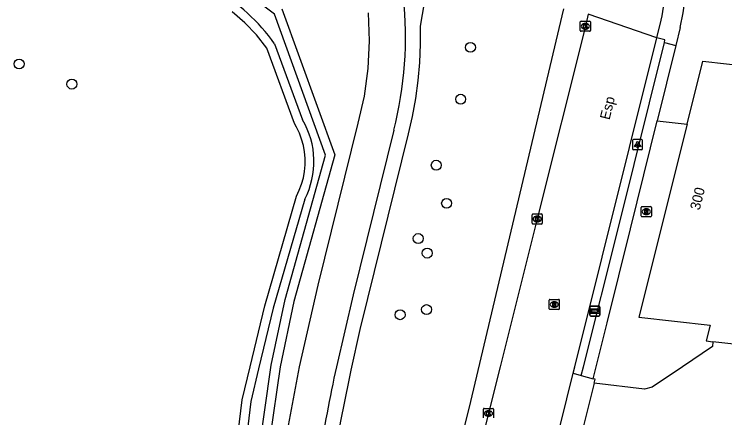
# Model space of a CAD drawing. Extents: x 161389 to 162585, y 388479 to 389761.
# Drawn here: x 162161.9 to 162232.2, y 388744.9 to 388784.9 of the extents above; entities that cross this region are included whole.
import ezdxf

# ---------------------------------------------------------------- set-up
doc = ezdxf.new("R2010")
doc.units = 0
for name, color, linetype in [('IMGEO_Berm_groen', 7, 'Continuous'), ('IMGEO_Boom', 7, 'Continuous'), ('IMGEO_Fietspad_gesloten', 7, 'Continuous'), ('IMGEO_Groenvoorziening', 7, 'Continuous'), ('IMGEO_Kolk', 7, 'Continuous'), ('IMGEO_Lichtpunt', 7, 'Continuous'), ('IMGEO_Openbare_ruimte_label', 7, 'Continuous'), ('IMGEO_Pand', 7, 'Continuous'), ('IMGEO_Pand_nummerreeks', 7, 'Continuous'), ('IMGEO_Rijbaan_lokaal_gesloten', 7, 'Continuous'), ('IMGEO_Rioolput', 7, 'Continuous'), ('IMGEO_Voetpad_open', 7, 'Continuous'), ('IMGEO_Waterloop', 7, 'Continuous'), ('IMGEO_Wegwijzer', 7, 'Continuous')]:
    doc.layers.add(name, color=color, linetype=linetype)

msp = doc.modelspace()

# ---------------------------------------------------------------- linework, layer by layer
at = {"layer": 'IMGEO_Berm_groen'}
for points in [[(162191.86, 388718.037), (162191.886, 388722.099), (162191.891, 388724.822), (162191.975, 388727.523), (162192.137, 388730.219), (162192.378, 388732.909), (162192.697, 388735.591), (162193.094, 388738.264), (162193.499, 388740.561), (162194.225, 388744.62), (162195.027, 388748.658), (162195.242, 388749.672), (162196.145, 388753.699), (162196.882, 388756.748), (162200.909, 388773.061), (162201.309, 388774.777), (162201.634, 388776.543), (162201.879, 388778.321), (162202.04, 388780.111), (162202.118, 388781.905), (162202.114, 388783.702), (162202.484, 388786.004)], [(162216.273, 388785.418), (162206.891, 388745.858), (162201.753, 388725.36), (162199.91, 388717.985), (162191.86, 388718.037)]]:
    msp.add_lwpolyline(points, dxfattribs=at)
at = {"layer": 'IMGEO_Boom'}
for centre in [(162207.051, 388781.607), (162162.37, 388779.96), (162167.587, 388777.964), (162206.084, 388776.477), (162203.663, 388769.943), (162204.685, 388766.173), (162201.877, 388762.686), (162202.768, 388761.243), (162202.7, 388755.656), (162200.089, 388755.143)]:
    msp.add_circle(centre, 0.489, dxfattribs=at)
at = {"layer": 'IMGEO_Fietspad_gesloten'}
for points in [[(162186.329, 388700.295), (162186.802, 388723.126), (162187.239, 388731.997), (162188.536, 388741.532), (162190.109, 388750), (162191.97, 388758.076), (162195.928, 388774.095), (162196.55, 388776.78), (162196.93, 388779.509), (162197.064, 388782.261), (162196.952, 388785.015)], [(162199.448, 388773.401), (162195.426, 388757.107), (162193.778, 388750)]]:
    msp.add_lwpolyline(points, dxfattribs=at)
for centre, radius, start, end in [((162163.354, 388782.698), 37.273, 345.55573, 5.99964), ((162403.128, 388705.189), 214.092, 167.91817, 170.41916)]:
    msp.add_arc(centre, radius, start, end, dxfattribs=at)
at = {"layer": 'IMGEO_Groenvoorziening'}
for points in [[(162188.39, 388785.424), (162193.632, 388770.975), (162189.553, 388756.443), (162188.194, 388750), (162186.166, 388735.884), (162185.429, 388723.281), (162185.919, 388717.086), (162185.324, 388714.25), (162184.667, 388702.506)], [(162181.617, 388706.073), (162182.042, 388714.232), (162182.441, 388730.142), (162184.437, 388746.716), (162185.228, 388750), (162186.682, 388756.035), (162189.827, 388766.893), (162190.106, 388767.475), (162190.333, 388768.079), (162190.504, 388768.701), (162190.619, 388769.336), (162190.677, 388769.979), (162190.678, 388770.624), (162190.62, 388771.267), (162190.506, 388771.902), (162190.335, 388772.525), (162190.109, 388773.129), (162189.831, 388773.711), (162189.63, 388774.062), (162186.881, 388781.532), (162185.852, 388782.834), (162184.71, 388784.039), (162183.465, 388785.137)], [(162225.536, 388774.348), (162228.503, 388774.016)], [(162231.056, 388752.479), (162231.003, 388751.998), (162228.046, 388750), (162225.043, 388747.971), (162224.275, 388747.77), (162219.301, 388748.377)]]:
    msp.add_lwpolyline(points, dxfattribs=at)
at = {"layer": 'IMGEO_Kolk'}
for p, q in [((162217.921, 388783.266), (162217.921, 388784.118)), ((162217.996, 388784.192), (162218.848, 388784.192)), ((162218.409, 388783.972), (162218.434, 388783.972)), ((162218.922, 388784.118), (162218.922, 388783.266)), ((162218.848, 388783.192), (162217.996, 388783.192)), ((162218.432, 388783.412), (162218.407, 388783.412)), ((162213.157, 388764.194), (162213.157, 388765.046)), ((162213.232, 388765.12), (162214.084, 388765.12)), ((162213.645, 388764.9), (162213.67, 388764.9)), ((162214.158, 388765.046), (162214.158, 388764.194)), ((162213.668, 388764.34), (162213.643, 388764.34)), ((162214.084, 388764.12), (162213.232, 388764.12)), ((162208.329, 388744.947), (162208.329, 388745.799)), ((162208.404, 388745.873), (162209.256, 388745.873)), ((162208.817, 388745.653), (162208.842, 388745.653)), ((162209.33, 388745.799), (162209.33, 388744.947)), ((162208.84, 388745.093), (162208.815, 388745.093))]:
    msp.add_line(p, q, dxfattribs=at)
for points in [[(162217.921, 388783.266), (162217.921, 388784.118)], [(162217.996, 388784.192), (162218.848, 388784.192)], [(162218.242, 388783.892), (162218.365, 388783.892), (162218.365, 388783.741), (162218.495, 388783.892), (162218.659, 388783.892), (162218.513, 388783.741), (162218.666, 388783.492), (162218.514, 388783.492), (162218.429, 388783.656), (162218.365, 388783.589), (162218.365, 388783.492), (162218.242, 388783.492), (162218.242, 388783.892)], [(162218.922, 388784.118), (162218.922, 388783.266)], [(162218.848, 388783.192), (162217.996, 388783.192)], [(162213.157, 388764.194), (162213.157, 388765.046)], [(162213.232, 388765.12), (162214.084, 388765.12)], [(162214.158, 388765.046), (162214.158, 388764.194)], [(162213.478, 388764.82), (162213.601, 388764.82), (162213.601, 388764.669), (162213.731, 388764.82), (162213.895, 388764.82), (162213.749, 388764.669), (162213.902, 388764.42), (162213.75, 388764.42), (162213.665, 388764.584), (162213.601, 388764.517), (162213.601, 388764.42), (162213.478, 388764.42), (162213.478, 388764.82)], [(162214.084, 388764.12), (162213.232, 388764.12)], [(162208.329, 388744.947), (162208.329, 388745.799)], [(162208.404, 388745.873), (162209.256, 388745.873)], [(162208.65, 388745.573), (162208.773, 388745.573), (162208.773, 388745.422), (162208.903, 388745.573), (162209.067, 388745.573), (162208.921, 388745.422), (162209.074, 388745.173), (162208.922, 388745.173), (162208.837, 388745.337), (162208.773, 388745.27), (162208.773, 388745.173), (162208.65, 388745.173), (162208.65, 388745.573)], [(162209.33, 388745.799), (162209.33, 388744.947)]]:
    msp.add_lwpolyline(points, dxfattribs=at)
for centre, start, end in [((162217.998, 388784.116), 91.55205, 178.44795), ((162217.998, 388784.116), 91.55205, 178.44795), ((162218.846, 388784.116), 1.55205, 88.44795), ((162218.846, 388784.116), 1.55205, 88.44795), ((162217.998, 388783.268), 181.55205, 268.44795), ((162217.998, 388783.268), 181.55205, 268.44795), ((162218.846, 388783.268), 271.55205, 358.44795), ((162218.846, 388783.268), 271.55205, 358.44795), ((162213.234, 388765.044), 91.55205, 178.44795), ((162213.234, 388765.044), 91.55205, 178.44795), ((162214.082, 388765.044), 1.55205, 88.44795), ((162214.082, 388765.044), 1.55205, 88.44795), ((162213.234, 388764.196), 181.55205, 268.44795), ((162213.234, 388764.196), 181.55205, 268.44795), ((162214.082, 388764.196), 271.55205, 358.44795), ((162214.082, 388764.196), 271.55205, 358.44795), ((162208.406, 388745.797), 91.55205, 178.44795), ((162208.406, 388745.797), 91.55205, 178.44795), ((162209.254, 388745.797), 1.55205, 88.44795), ((162209.254, 388745.797), 1.55205, 88.44795)]:
    msp.add_arc(centre, 0.0765, start, end, dxfattribs=at)
for centre, major_axis, ratio, start_param, end_param in [((162218.408, 388783.692), (-0.387, 0.002), 0.722429, 4.712389, 7.853982), ((162218.433, 388783.692), (-0.39, 0.002), 0.717154, 1.570796, 4.712389), ((162213.644, 388764.62), (-0.387, 0.002), 0.722429, 4.712389, 7.853982), ((162213.669, 388764.62), (-0.39, 0.002), 0.717154, 1.570796, 4.712389), ((162208.816, 388745.373), (-0.387, 0.002), 0.722429, 4.712389, 7.853982), ((162208.841, 388745.373), (-0.39, 0.002), 0.717154, 1.570796, 4.712389)]:
    msp.add_ellipse(centre, major_axis=major_axis, ratio=ratio, start_param=start_param, end_param=end_param, dxfattribs=at)
at = {"layer": 'IMGEO_Lichtpunt'}
for p, q in [((162223.09, 388772.382), (162223.09, 388771.575)), ((162223.09, 388772.382), (162223.09, 388771.575)), ((162223.992, 388772.477), (162223.184, 388772.477)), ((162223.992, 388772.477), (162223.184, 388772.477)), ((162224.086, 388771.575), (162224.086, 388772.382)), ((162224.086, 388771.575), (162224.086, 388772.382)), ((162223.184, 388771.481), (162223.992, 388771.481)), ((162223.184, 388771.481), (162223.992, 388771.481))]:
    msp.add_line(p, q, dxfattribs=at)
for points in [[(162223.464, 388772.046), (162223.503, 388772.018), (162223.315, 388771.756), (162223.277, 388771.783), (162223.464, 388772.046)], [(162223.566, 388771.998), (162223.613, 388771.998), (162223.613, 388771.676), (162223.566, 388771.676), (162223.566, 388771.998)], [(162223.676, 388772.018), (162223.714, 388772.045), (162223.901, 388771.783), (162223.862, 388771.755), (162223.676, 388772.018)]]:
    msp.add_lwpolyline(points, dxfattribs=at)
msp.add_circle((162223.589, 388772.18), 0.0994, dxfattribs=at)
for centre, start, end in [((162223.184, 388772.382), 90, 180), ((162223.184, 388772.382), 90, 180), ((162223.992, 388772.382), 0, 90), ((162223.992, 388772.382), 0, 90), ((162223.184, 388771.575), 180, 270), ((162223.184, 388771.575), 180, 270), ((162223.992, 388771.575), 270, 0), ((162223.992, 388771.575), 270, 360)]:
    msp.add_arc(centre, 0.0946, start, end, dxfattribs=at)
at = {"layer": 'IMGEO_Pand'}
for points in [[(162228.503, 388774.016), (162230.061, 388780.237), (162237.092, 388779.451), (162238.05, 388783.23), (162279.094, 388778.662), (162275.602, 388747.53), (162231.056, 388752.479)], [(162228.503, 388774.016), (162223.716, 388754.893), (162230.79, 388754.121), (162230.389, 388752.553), (162231.056, 388752.479)]]:
    msp.add_lwpolyline(points, dxfattribs=at)
at = {"layer": 'IMGEO_Rijbaan_lokaal_gesloten'}
for points in [[(162218.716, 388784.885), (162218.423, 388783.692), (162213.659, 388764.62), (162209.992, 388750), (162203.693, 388724.874), (162198.604, 388704.506), (162198.376, 388703.539)], [(162225.506, 388782.552), (162218.716, 388784.885)], [(162225.506, 388782.552), (162225.943, 388784.303)], [(162217.225, 388749.348), (162217.388, 388750), (162225.506, 388782.552)], [(162215.296, 388741.611), (162217.225, 388749.348)]]:
    msp.add_lwpolyline(points, dxfattribs=at)
msp.add_arc((162200.611, 388789.538), 25.868, 348.32437, 3.5354, dxfattribs=at)
at = {"layer": 'IMGEO_Rioolput'}
for p, q in [((162223.957, 388764.916), (162223.957, 388765.768)), ((162224.032, 388765.842), (162224.884, 388765.842)), ((162224.445, 388765.622), (162224.47, 388765.622)), ((162224.958, 388765.768), (162224.958, 388764.916)), ((162224.468, 388765.062), (162224.443, 388765.062)), ((162224.884, 388764.842), (162224.032, 388764.842)), ((162214.847, 388755.732), (162214.847, 388756.584)), ((162214.922, 388756.658), (162215.774, 388756.658)), ((162215.848, 388756.584), (162215.848, 388755.732)), ((162215.358, 388755.878), (162215.333, 388755.878)), ((162215.335, 388756.438), (162215.36, 388756.438)), ((162215.774, 388755.658), (162214.922, 388755.658))]:
    msp.add_line(p, q, dxfattribs=at)
for points in [[(162223.957, 388764.916), (162223.957, 388765.768)], [(162224.032, 388765.842), (162224.884, 388765.842)], [(162224.958, 388765.768), (162224.958, 388764.916)], [(162224.546, 388765.54), (162224.294, 388765.542), (162224.294, 388765.142)], [(162224.294, 388765.142), (162224.418, 388765.142), (162224.418, 388765.304), (162224.429, 388765.304)], [(162224.472, 388765.461), (162224.418, 388765.461), (162224.418, 388765.38)], [(162224.418, 388765.38), (162224.47, 388765.38)], [(162224.476, 388765.275), (162224.547, 388765.142), (162224.687, 388765.142), (162224.622, 388765.268)], [(162224.884, 388764.842), (162224.032, 388764.842)], [(162214.847, 388755.732), (162214.847, 388756.584)], [(162214.922, 388756.658), (162215.774, 388756.658)], [(162215.848, 388756.584), (162215.848, 388755.732)], [(162215.436, 388756.356), (162215.184, 388756.358), (162215.184, 388755.958)], [(162215.184, 388755.958), (162215.308, 388755.958), (162215.308, 388756.12), (162215.319, 388756.12)], [(162215.362, 388756.277), (162215.308, 388756.277), (162215.308, 388756.196)], [(162215.308, 388756.196), (162215.36, 388756.196)], [(162215.366, 388756.091), (162215.437, 388755.958), (162215.577, 388755.958), (162215.512, 388756.084)], [(162215.774, 388755.658), (162214.922, 388755.658)]]:
    msp.add_lwpolyline(points, dxfattribs=at)
for centre, radius, start, end in [((162224.034, 388765.766), 0.0765, 91.55205, 178.44795), ((162224.034, 388765.766), 0.0765, 91.55205, 178.44795), ((162224.882, 388765.766), 0.0765, 1.55205, 88.44795), ((162224.882, 388765.766), 0.0765, 1.55205, 88.44795), ((162224.034, 388764.918), 0.0765, 181.55205, 268.44795), ((162224.034, 388764.918), 0.0765, 181.55205, 268.44795), ((162224.428, 388765.251), 0.0533, 26.02933, 88.69889), ((162224.454, 388765.569), 0.19, 274.7715, 282.96867), ((162224.478, 388765.365), 0.0964, 77.00612, 93.18647), ((162224.492, 388765.422), 0.0378, 276.66336, 79.67722), ((162224.545, 388765.43), 0.109, 350.36119, 89.41601), ((162224.543, 388765.43), 0.112, 277.58423, 350.98172), ((162224.527, 388765.215), 0.108, 29.51342, 73.79051), ((162224.882, 388764.918), 0.0765, 271.55205, 358.44795), ((162224.882, 388764.918), 0.0765, 271.55205, 358.44795), ((162214.924, 388756.582), 0.0765, 91.55205, 178.44795), ((162214.924, 388756.582), 0.0765, 91.55205, 178.44795), ((162215.772, 388756.582), 0.0765, 1.55205, 88.44795), ((162215.772, 388756.582), 0.0765, 1.55205, 88.44795), ((162215.318, 388756.067), 0.0533, 26.02933, 88.69889), ((162215.344, 388756.385), 0.19, 274.7715, 282.96867), ((162215.368, 388756.181), 0.0964, 77.00612, 93.18647), ((162215.382, 388756.238), 0.0378, 276.66336, 79.67722), ((162215.435, 388756.246), 0.109, 350.36119, 89.41601), ((162215.433, 388756.246), 0.112, 277.58423, 350.98172), ((162215.417, 388756.031), 0.108, 29.51342, 73.79051), ((162214.924, 388755.734), 0.0765, 181.55205, 268.44795), ((162214.924, 388755.734), 0.0765, 181.55205, 268.44795), ((162215.772, 388755.734), 0.0765, 271.55205, 358.44795), ((162215.772, 388755.734), 0.0765, 271.55205, 358.44795)]:
    msp.add_arc(centre, radius, start, end, dxfattribs=at)
for centre, major_axis, ratio, start_param, end_param in [((162224.444, 388765.342), (-0.387, 0.002), 0.722429, 4.712389, 7.853982), ((162224.469, 388765.342), (-0.39, 0.002), 0.717154, 1.570796, 4.712389), ((162215.334, 388756.158), (-0.387, 0.002), 0.722429, 4.712389, 7.853982), ((162215.359, 388756.158), (-0.39, 0.002), 0.717154, 1.570796, 4.712389)]:
    msp.add_ellipse(centre, major_axis=major_axis, ratio=ratio, start_param=start_param, end_param=end_param, dxfattribs=at)
at = {"layer": 'IMGEO_Voetpad_open'}
for points in [[(162227.821, 388783.586), (162227.379, 388781.799)], [(162226.256, 388782.09), (162226.294, 388782.351), (162225.506, 388782.552)], [(162218.017, 388749.135), (162218.235, 388750), (162221.767, 388764.036), (162226.256, 388782.09)], [(162227.379, 388781.799), (162225.536, 388774.348)], [(162226.256, 388782.09), (162227.379, 388781.799)], [(162219.2, 388748.817), (162219.494, 388750), (162220.571, 388754.329), (162222.892, 388763.659), (162225.536, 388774.348)], [(162217.225, 388749.348), (162218.017, 388749.135)], [(162218.017, 388749.135), (162219.2, 388748.817)], [(162219.301, 388748.377), (162219.404, 388748.762), (162219.2, 388748.817)], [(162219.301, 388748.377), (162217.745, 388742.187)]]:
    msp.add_lwpolyline(points, dxfattribs=at)
msp.add_arc((162201.265, 388789.602), 27.228, 347.2353, 3.60684, dxfattribs=at)
at = {"layer": 'IMGEO_Waterloop'}
for points in [[(162183.935, 388699.637), (162183.687, 388700.43), (162183.794, 388702.552), (162184.455, 388714.365), (162185.037, 388717.142), (162184.552, 388723.272), (162185.295, 388735.972), (162187.332, 388750.153), (162188.703, 388756.652), (162192.714, 388770.941), (162187.655, 388784.885), (162184.725, 388787.123), (162183.897, 388787.97), (162183.246, 388788.961), (162183.097, 388789.284)], [(162187.654, 388781.965), (162190.425, 388774.433)], [(162190.647, 388766.58), (162187.528, 388755.811), (162186.078, 388749.795), (162185.299, 388746.561), (162183.314, 388730.079), (162182.916, 388714.198), (162182.486, 388705.941), (162181.646, 388702.644), (162181.262, 388699.18)]]:
    msp.add_lwpolyline(points, dxfattribs=at)
for centre, radius, start, end in [((162171.764, 388770.599), 19.536, 35.57668, 59.28137), ((162183.496, 388770.307), 8.064, 332.46903, 30.76955)]:
    msp.add_arc(centre, radius, start, end, dxfattribs=at)
at = {"layer": 'IMGEO_Wegwijzer'}
for p, q in [((162218.855, 388755.109), (162218.855, 388755.909)), ((162218.855, 388755.909), (162218.855, 388755.109)), ((162218.955, 388756.009), (162219.745, 388756.009)), ((162219.745, 388756.009), (162218.955, 388756.009)), ((162219.845, 388755.909), (162219.845, 388755.109)), ((162219.845, 388755.109), (162219.845, 388755.909)), ((162219.745, 388755.009), (162218.955, 388755.009)), ((162218.955, 388755.009), (162219.745, 388755.009))]:
    msp.add_line(p, q, dxfattribs=at)
for points in [[(162218.956, 388755.741), (162219.744, 388755.741), (162219.744, 388755.277), (162218.956, 388755.277), (162218.956, 388755.741)], [(162219.021, 388755.593), (162219.021, 388755.509), (162219.021, 388755.425), (162219.432, 388755.425), (162219.432, 388755.342), (162219.679, 388755.509), (162219.432, 388755.676), (162219.432, 388755.593), (162219.021, 388755.593)]]:
    msp.add_lwpolyline(points, dxfattribs=at)
for centre, start, end in [((162218.955, 388755.909), 90, 180), ((162218.955, 388755.909), 90, 180), ((162219.745, 388755.909), 0, 90), ((162219.745, 388755.909), 360, 90), ((162218.955, 388755.109), 180, 270), ((162218.955, 388755.109), 180, 270), ((162219.745, 388755.109), 270, 0), ((162219.745, 388755.109), 270, 0)]:
    msp.add_arc(centre, 0.1, start, end, dxfattribs=at)

# ---------------------------------------------------------------- texts
at = {"layer": 'IMGEO_Openbare_ruimte_label'}
msp.add_text('Esp', height=1, rotation=75.99156, dxfattribs=at).set_placement((162220.812, 388774.371))
at = {"layer": 'IMGEO_Pand_nummerreeks'}
msp.add_text('300', height=1, rotation=75.94495, dxfattribs=at).set_placement((162229.737, 388765.437))

doc.saveas('drawing.dxf')
